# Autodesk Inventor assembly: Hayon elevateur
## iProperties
Shininess: 64.0
Length Units: 11269
Angle Units: 11279
Time Units: 11290
Mass Units: 11283
Length Display Precision: 3
Angle Display Precision: 2
Compacted: True
Created: 2006-11
Part Number: Hayon elevateur
Document SubType Name: Assembly
Designer: profs_sti
Density: 0.0
Volumn: 0.0
Area: 0.0
PropertySet Name: Model Information
Control State: 0
Master: False
Checked Out: False
Norme de conversion: STEP AP214DIS
Nom du fichier: Assemblage.STEP
Préprocesseur: SolidWorks 2005204
Postprocesseur: Build: 120c, Release: 6 SP2 - Date: Mon 01/13/2003
Unités envoyées: MILLIMETERS
Incertitude: 0.0
Author: profs_sti
